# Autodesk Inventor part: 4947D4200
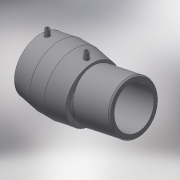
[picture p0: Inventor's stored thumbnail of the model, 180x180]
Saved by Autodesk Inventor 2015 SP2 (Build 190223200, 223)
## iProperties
Created: 2017-06
Part Number: 4947D4200
Material: Generic
Description: PLASSON ADJUSTABLE ELBOW (ONE SIDE) 200
Document SubType Name: Modeling
Designer: KIM
Mass: 5664.07 g
Surface Area: 5234.03 cm^2
Volume: 5664.07 cm^3
Density: 1 g/cm^3
Appearance: Default
Author: KIM
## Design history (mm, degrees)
derived "4947D4.ipt"
feature "Solid1::4947D4.ipt"
tag "TaggingFeature1"
body "Solid1"
other parameters: "d0" = 194.25, "d3" = 104, "d4" = 52, "d5" = 225, "d8" = 168 deg, "d10" = 41.6, "d11" = 13.86667, "d29" = 125, "d30" = 15, "d31" = 74, "d34" = 5 deg, "d41" = 4, "d42" = 14, "d43" = 0, "d55" = 54.15, "d57" = 168 deg, "d62" = 3, "d63" = 0, "d68" = 135 deg, "d69" = 116, "d70" = 92.5, "d71" = 5, "L_1" = 104, "A_" = 125, "d_2" = 12, "L_0" = 148, "L_2" = 116, "d54" = 90.25, "d59" = 230.09945
